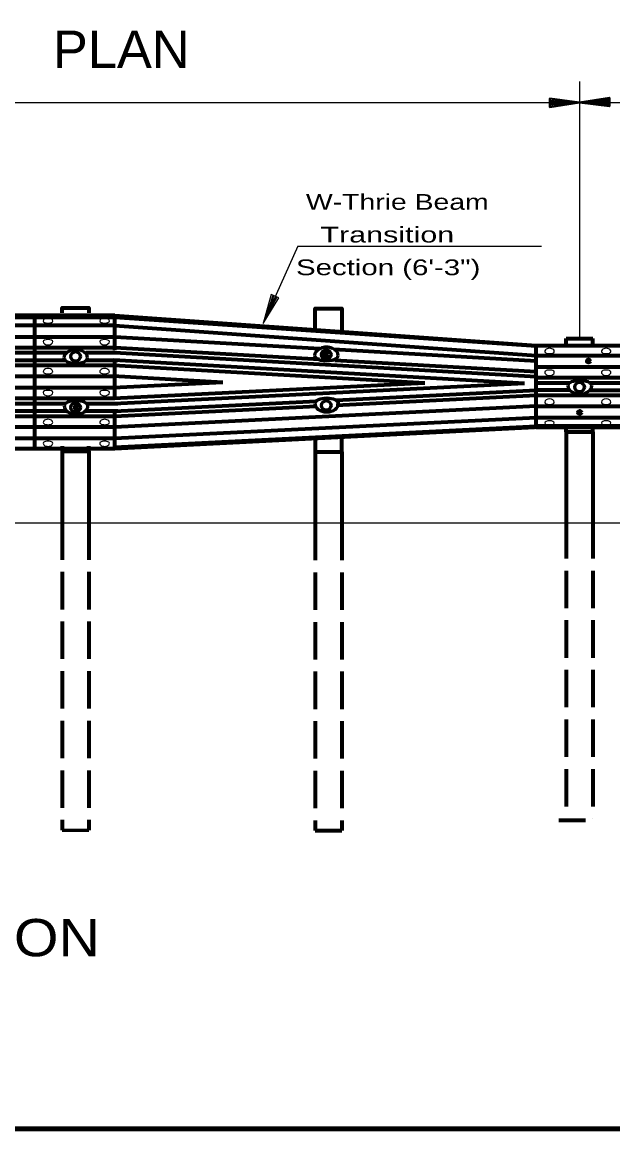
# Model space of a CAD drawing. Extents: x 856.9 to 891.7, y -2278.5 to -2254.7.
# Drawn here: x 872.97 to 877.8, y -2277.16 to -2268.1 of the extents above; entities that cross this region are included whole.
import ezdxf
from ezdxf.enums import TextEntityAlignment as Align

# ---------------------------------------------------------------- set-up
doc = ezdxf.new("R2010")
doc.units = 0
doc.header["$LTSCALE"] = 0.051
doc.header["$PDMODE"] = 32
doc.header["$PDSIZE"] = 0.0255
doc.linetypes.add('LONG_DASHED', pattern=[7.5, 6, -1.5])
for name, color, linetype, lineweight in [('1', 7, 'Continuous', 70), ('3', 7, 'Continuous', 40), ('35', 7, 'Continuous', 70)]:
    doc.layers.add(name, color=color, linetype=linetype, lineweight=lineweight)

msp = doc.modelspace()

# ---------------------------------------------------------------- linework, layer by layer
at = {"layer": '1', "lineweight": 25}
for p, q in [((877.53042, -2268.5895), (877.53042, -2270.69533)), ((865.22225, -2268.76158), (877.53042, -2268.76158)), ((877.53042, -2268.76158), (880.50733, -2268.76158)), ((875.22417, -2269.93942), (874.93842, -2270.57167)), ((875.22417, -2269.93942), (877.219, -2269.93942)), ((862.12625, -2272.20317), (882.07667, -2272.20317))]:
    msp.add_line(p, q, dxfattribs=at)
at = {"layer": '1'}
for p, q in [((873.7235, -2270.5055), (865.61775, -2270.5055)), ((873.06783, -2270.5055), (873.06783, -2271.59675)), ((873.7235, -2270.5055), (877.175, -2270.75233)), ((865.61775, -2270.51925), (873.7235, -2270.51925)), ((873.7235, -2270.58867), (865.61775, -2270.58867)), ((873.7235, -2270.51925), (877.17383, -2270.75433)), ((873.7235, -2270.58867), (877.175, -2270.833)), ((873.7235, -2270.68233), (867.41158, -2270.68233)), ((875.40408, -2270.77892), (873.7235, -2270.68233)), ((873.7235, -2270.77067), (867.41158, -2270.77067)), ((875.40042, -2270.86583), (873.7235, -2270.77067)), ((877.175, -2270.88083), (875.51775, -2270.78525)), ((877.175, -2271.42042), (877.175, -2270.75233)), ((877.175, -2270.75233), (882.07667, -2270.75233)), ((873.32717, -2270.81267), (871.38492, -2270.81267)), ((873.32717, -2270.8735), (871.38492, -2270.8735)), ((873.7235, -2270.81267), (873.491, -2270.81267)), ((873.72158, -2270.81267), (873.491, -2270.81267)), ((873.75033, -2270.8735), (873.491, -2270.8735)), ((873.7235, -2270.8735), (873.491, -2270.8735)), ((877.07808, -2271.0635), (873.7175, -2270.87225)), ((877.175, -2271.00917), (873.721, -2270.81192)), ((877.175, -2270.96708), (875.52692, -2270.87333)), ((877.175, -2270.833), (882.07667, -2270.833)), ((873.7235, -2270.91617), (865.61775, -2270.91617)), ((876.262, -2271.06092), (873.71492, -2270.91542)), ((877.175, -2270.92717), (882.07667, -2270.92717)), ((873.7235, -2271.004), (865.61775, -2271.004)), ((874.61033, -2271.055), (873.71025, -2271.00333)), ((874.61033, -2271.055), (873.71158, -2271.09883)), ((877.175, -2271.01367), (882.07667, -2271.01367)), ((877.175, -2271.05683), (877.44933, -2271.05683)), ((877.6105, -2271.05683), (879.466, -2271.05683)), ((873.73325, -2271.09817), (865.61775, -2271.09817)), ((876.262, -2271.06092), (873.71625, -2271.18667)), ((877.07808, -2271.0635), (873.71825, -2271.22992)), ((877.175, -2271.12042), (875.53817, -2271.20175)), ((877.17242, -2271.1185), (877.16708, -2271.1185)), ((877.44933, -2271.1185), (877.18292, -2271.1185)), ((873.7235, -2271.18667), (865.61775, -2271.18667)), ((873.32717, -2271.22833), (871.38492, -2271.22833)), ((873.75033, -2271.22833), (873.491, -2271.22833)), ((875.374, -2271.20958), (873.72158, -2271.29142)), ((877.175, -2271.16117), (875.537, -2271.24225)), ((873.32717, -2271.29017), (871.38492, -2271.29017)), ((873.75033, -2271.29017), (873.491, -2271.29017)), ((873.7235, -2271.29017), (873.491, -2271.29017)), ((877.175, -2271.24942), (873.7235, -2271.42042)), ((875.37458, -2271.25017), (873.7235, -2271.33208)), ((877.175, -2271.2475), (882.07667, -2271.2475)), ((873.7235, -2271.33208), (865.61775, -2271.33208)), ((873.7235, -2271.42042), (865.61775, -2271.42042)), ((877.175, -2271.34383), (873.7235, -2271.51333)), ((873.7235, -2271.58283), (877.17383, -2271.41067)), ((877.21633, -2271.42042), (873.7235, -2271.59675)), ((877.17242, -2271.42042), (882.07667, -2271.42042)), ((882.07667, -2271.41067), (877.17383, -2271.41067)), ((877.175, -2271.34183), (882.07667, -2271.34183)), ((877.42133, -2271.45892), (877.42133, -2272.18867)), ((877.6395, -2271.45892), (877.6395, -2272.18867)), ((873.7235, -2271.59675), (864.03558, -2271.59675)), ((873.7235, -2271.51333), (865.61775, -2271.51333)), ((873.29408, -2271.6175), (873.29408, -2272.19925)), ((873.51208, -2271.6175), (873.51208, -2272.19925)), ((875.36425, -2271.62142), (875.36425, -2272.20317)), ((875.5825, -2271.62142), (875.5825, -2272.20317))]:
    msp.add_line(p, q, dxfattribs=at)
at = {"layer": '1', "linetype": 'LONG_DASHED'}
for p, q in [((873.7235, -2271.60125), (873.7235, -2270.5055)), ((873.29408, -2272.19925), (873.29408, -2274.71817)), ((873.51208, -2272.19925), (873.51208, -2274.71817)), ((875.36425, -2272.20317), (875.36425, -2274.72208)), ((875.5825, -2272.20317), (875.5825, -2274.72208)), ((877.42133, -2272.18867), (877.42133, -2274.62508)), ((877.6395, -2272.18867), (877.6395, -2274.62508)), ((877.57783, -2274.63958), (877.35967, -2274.63958)), ((875.36425, -2274.72208), (875.5825, -2274.72208))]:
    msp.add_line(p, q, dxfattribs=at)
at = {"layer": '1', "lineweight": 13}
for p, q in [((873.75033, -2270.91617), (873.491, -2270.91617)), ((873.7175, -2271.22833), (873.491, -2271.22833)), ((865.61775, -2271.58283), (873.7235, -2271.58283))]:
    msp.add_line(p, q, dxfattribs=at)
at = {"layer": '1', "linetype": 'LONG_DASHED', "lineweight": 60}
msp.add_line((873.29408, -2274.71817), (873.51208, -2274.71817), dxfattribs=at)
at = {"layer": '1', "lineweight": 40}
for points in [[(877.53042, -2268.76158), (877.28617, -2268.73025), (877.28617, -2268.80033)], [(877.53042, -2268.76158), (877.77475, -2268.79308), (877.77475, -2268.72308)]]:
    msp.add_lwpolyline(points, close=True, dxfattribs=at)
for points in [[(877.28617, -2268.74792), (877.46942, -2268.76158), (877.28617, -2268.78258)], [(877.28617, -2268.75642), (877.37325, -2268.76358), (877.28617, -2268.77408)], [(877.77475, -2268.77542), (877.59133, -2268.76158), (877.77475, -2268.74067)], [(877.77475, -2268.767), (877.68767, -2268.75975), (877.77475, -2268.74925)]]:
    msp.add_lwpolyline(points, dxfattribs=at)
at = {"layer": '1', "lineweight": 25}
msp.add_lwpolyline([(874.93842, -2270.57167), (875.06742, -2270.362), (875.00383, -2270.33325)], close=True, dxfattribs=at)
for points in [[(875.05167, -2270.35492), (874.96333, -2270.516), (875.02025, -2270.3405)], [(875.04392, -2270.35083), (875.00125, -2270.42758), (875.02808, -2270.34367)]]:
    msp.add_lwpolyline(points, dxfattribs=at)
at = {"layer": '1'}
for points in [[(873.29408, -2270.48517), (873.29408, -2270.44392), (873.51208, -2270.44392), (873.51208, -2270.48517)], [(875.36425, -2270.62592), (875.36425, -2270.44783), (875.5825, -2270.44783), (875.5825, -2270.63242)], [(877.61192, -2271.1185), (879.466, -2271.1185), (881.52725, -2271.1185)], [(877.175, -2271.15917), (877.38067, -2271.15917), (882.07667, -2271.15917)], [(875.36425, -2271.518), (875.36425, -2271.62142), (875.5825, -2271.62142), (875.5825, -2271.50692)], [(873.29408, -2271.57633), (873.29408, -2271.6175), (873.51208, -2271.6175), (873.51208, -2271.57633)]]:
    msp.add_lwpolyline(points, dxfattribs=at)
at = {"layer": '1', "lineweight": 60}
for centre in [(873.40304, -2270.84093), (875.45596, -2270.82612), (877.53013, -2271.09183), (873.40312, -2271.25904), (875.45596, -2271.24214)]:
    msp.add_circle(centre, 0.03923, dxfattribs=at)
at = {"layer": '1', "lineweight": 25}
for centre, major_axis, ratio, start_param, end_param in [((873.17723, -2270.55127), (-0.03921, 0), 0.679978, 3.1415927, 6.2831853), ((873.17723, -2270.55127), (0.03921, 0), 0.434256, 3.1415927, 6.2831853), ((873.64096, -2270.55127), (-0.03921, 0), 0.679978, 3.1415927, 6.2831853), ((873.64096, -2270.55127), (0.03921, 0), 0.434256, 3.1415927, 6.2831853), ((873.17723, -2270.71983), (-0.03921, 0), 0.442883, 3.1415927, 6.2831853), ((873.17723, -2270.71983), (0.03921, 0), 0.696674, 3.1415927, 6.2831853), ((873.64096, -2270.71983), (-0.03921, 0), 0.442883, 3.1415927, 6.2831853), ((873.64096, -2270.71983), (0.03921, 0), 0.696674, 3.1415927, 6.2831853), ((877.28439, -2270.8012), (0.03921, 0), 0.679978, 6.2831853, 9.424778), ((877.74813, -2270.8012), (0.03921, 0), 0.679978, 6.2831853, 9.424778), ((877.28439, -2270.8012), (-0.03921, 0), 0.434256, 6.2831853, 9.424778), ((877.74813, -2270.8012), (-0.03921, 0), 0.434256, 6.2831853, 9.424778), ((873.17723, -2270.96642), (0.03921, 0), 0.696674, 6.2831853, 9.424778), ((873.17723, -2270.96642), (-0.03921, 0), 0.442883, 6.2831853, 9.424778), ((873.64096, -2270.96642), (0.03921, 0), 0.696674, 6.2831853, 9.424778), ((873.64096, -2270.96642), (-0.03921, 0), 0.442883, 6.2831853, 9.424778), ((877.28439, -2270.96976), (0.03921, 0), 0.442883, 6.2831853, 9.424778), ((877.74813, -2270.96976), (0.03921, 0), 0.442883, 6.2831853, 9.424778), ((877.28439, -2270.96976), (-0.03921, 0), 0.696674, 6.2831853, 9.424778), ((877.74813, -2270.96976), (-0.03921, 0), 0.696674, 6.2831853, 9.424778), ((873.17723, -2271.1359), (-0.03921, 0), 0.442883, 3.1415927, 6.2831853), ((873.17723, -2271.1359), (0.03921, 0), 0.696674, 3.1415927, 6.2831853), ((873.64096, -2271.1359), (-0.03921, 0), 0.442883, 3.1415927, 6.2831853), ((873.64096, -2271.1359), (0.03921, 0), 0.696674, 3.1415927, 6.2831853), ((877.28439, -2271.21635), (-0.03921, 0), 0.696674, 3.1415927, 6.2831853), ((877.28439, -2271.21635), (0.03921, 0), 0.442883, 3.1415927, 6.2831853), ((877.74813, -2271.21635), (-0.03921, 0), 0.696674, 3.1415927, 6.2831853), ((877.74813, -2271.21635), (0.03921, 0), 0.442883, 3.1415927, 6.2831853), ((873.17723, -2271.38249), (0.03921, 0), 0.696674, 6.2831853, 9.424778), ((873.17723, -2271.38249), (-0.03921, 0), 0.442883, 6.2831853, 9.424778), ((873.64096, -2271.38249), (0.03921, 0), 0.696674, 6.2831853, 9.424778), ((873.64096, -2271.38249), (-0.03921, 0), 0.442883, 6.2831853, 9.424778), ((877.28439, -2271.3849), (-0.03921, 0), 0.434256, 3.1415927, 6.2831853), ((877.28439, -2271.3849), (0.03921, 0), 0.679978, 3.1415927, 6.2831853), ((877.74813, -2271.3849), (-0.03921, 0), 0.434256, 3.1415927, 6.2831853), ((877.74813, -2271.3849), (0.03921, 0), 0.679978, 3.1415927, 6.2831853), ((873.17723, -2271.55105), (0.03921, 0), 0.434256, 6.2831853, 9.424778), ((873.17723, -2271.55105), (-0.03921, 0), 0.679978, 6.2831853, 9.424778), ((873.64096, -2271.55105), (0.03921, 0), 0.434256, 6.2831853, 9.424778), ((873.64096, -2271.55105), (-0.03921, 0), 0.679978, 6.2831853, 9.424778)]:
    msp.add_ellipse(centre, major_axis=major_axis, ratio=ratio, start_param=start_param, end_param=end_param, dxfattribs=at)
at = {"layer": '1', "lineweight": 60}
for centre, major_axis, ratio, start_param, end_param in [((873.40466, -2270.85353), (0.09753, 0), 0.696674, 0, 3.1415927), ((875.45733, -2270.83387), (0.09753, 0), 0.696674, 0, 3.1415927), ((873.40466, -2270.85353), (-0.09753, 0), 0.442883, 0, 3.1415927), ((875.45733, -2270.83387), (-0.09753, 0), 0.442883, 0, 3.1415927), ((877.53199, -2271.08072), (-0.09753, 0), 0.442883, 3.1415927, 6.2831853), ((877.53199, -2271.08072), (0.09753, 0), 0.696674, 3.1415927, 6.2831853), ((873.40683, -2271.24647), (-0.09753, 0), 0.442883, 3.1415927, 6.2831853), ((875.45949, -2271.22672), (-0.09753, 0), 0.442883, 3.1415927, 6.2831853), ((875.45949, -2271.22672), (0.09753, 0), 0.696674, 3.1415927, 6.2831853), ((873.40683, -2271.24647), (0.09753, 0), 0.696674, 3.1415927, 6.2831853)]:
    msp.add_ellipse(centre, major_axis=major_axis, ratio=ratio, start_param=start_param, end_param=end_param, dxfattribs=at)
at = {"layer": '1'}
for p in [(875.45575, -2270.82642), (877.60333, -2270.87883), (873.40908, -2271.25933), (877.53142, -2271.3)]:
    msp.add_point(p, dxfattribs=at)
at = {"layer": '3', "lineweight": 158}
msp.add_lwpolyline([(891.2, -2256.16333), (891.2, -2277.16333), (858.7, -2277.16333)], dxfattribs=at)
at = {"layer": '35'}
for p, q in [((877.42133, -2270.69533), (877.6395, -2270.69533)), ((877.42133, -2270.74308), (877.42133, -2270.69533)), ((877.6395, -2270.74308), (877.6395, -2270.69533)), ((877.42133, -2271.45892), (877.42133, -2271.41117)), ((877.6395, -2271.45892), (877.6395, -2271.41117)), ((877.42133, -2271.45892), (877.6395, -2271.45892))]:
    msp.add_line(p, q, dxfattribs=at)

# ---------------------------------------------------------------- texts
at = {"layer": '1'}
for s, width, p in [('PLAN', 1.05, (873.77738, -2268.47967)), ('ELEVATION', 1.15, (872.28521, -2275.75083))]:
    msp.add_text(s, height=0.3052, dxfattribs=dict(at, width=width)).set_placement(p, align=Align.CENTER)
for s, width, p in [('W-Thrie Beam', 1.35, (875.28967, -2269.64058)), (' Transition ', 1.45, (875.33933, -2269.90842)), ('Section (6\'-3")', 1.4, (875.20842, -2270.176))]:
    msp.add_text(s, height=0.1286, dxfattribs=dict(at, width=width)).set_placement(p)

doc.saveas('drawing.dxf')
